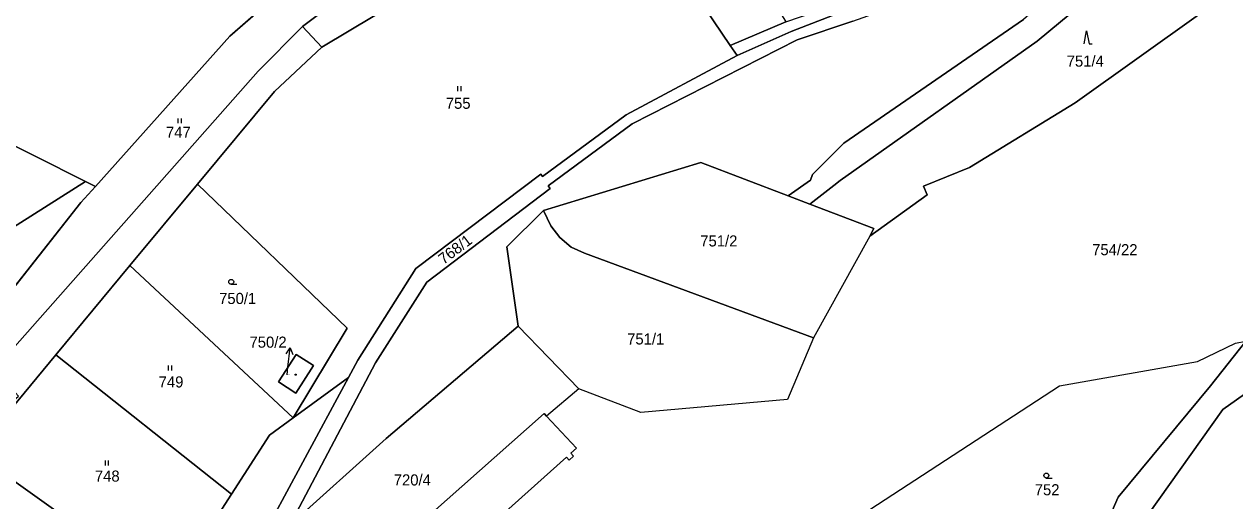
# Model space of a CAD drawing. Extents: x -598233 to -596890, y -1157848 to -1156431.
# Drawn here: x -597461.1 to -597275.6, y -1157216.3 to -1157143.3 of the extents above; entities that cross this region are included whole.
import ezdxf

# ---------------------------------------------------------------- set-up
doc = ezdxf.new("R2010")
doc.units = 0
for name, color, linetype in [('Level 1', 7, 'Continuous'), ('Level 4', 7, 'Continuous'), ('Level 5', 7, 'Continuous'), ('Level 57', 7, 'Continuous'), ('Level 60', 7, 'Continuous'), ('Vrstva 54', 7, 'Continuous'), ('Vrstva 60', 7, 'Continuous')]:
    doc.layers.add(name, color=color, linetype=linetype)

msp = doc.modelspace()

# ---------------------------------------------------------------- linework, layer by layer
at = {"layer": 'Level 1'}
for points in [[(-597420.41, -1157220.01), (-597407.32, -1157195.13), (-597399.45, -1157182.8), (-597380.53, -1157168.45), (-597380.82, -1157168.06), (-597367.96, -1157158.55), (-597342.68, -1157145.66), (-597334.13, -1157142.8), (-597316.39, -1157136.47), (-597308.16, -1157133.06), (-597297.58, -1157125.35), (-597289.89, -1157118.41), (-597284.19, -1157108.45), (-597281.93, -1157098.65), (-597282.12, -1157088.82), (-597281.12, -1157079.45), (-597275.24, -1157065.47), (-597273.04, -1157056.33), (-597273.21, -1157044.87), (-597272.14, -1157037.1)], [(-597272.14, -1157037.1), (-597265.05, -1157046.04), (-597261.79, -1157055.57), (-597266.72, -1157090.16), (-597273.93, -1157106.57), (-597277.61, -1157115.85), (-597307.94, -1157142.59), (-597335.53, -1157161.51), (-597340.31, -1157166.32), (-597340.61, -1157167.15), (-597344.04, -1157169.58)], [(-597450.24, -1157168.12), (-597429.64, -1157145.11), (-597411.66, -1157129.43), (-597398.16, -1157121.72), (-597386.77, -1157115.26), (-597350.78, -1157099.58), (-597323.95, -1157090.2), (-597313.81, -1157082.16), (-597315.54, -1157068.55), (-597316.36, -1157049.69)], [(-597351.85, -1157148.1), (-597343.59, -1157144.39), (-597334.76, -1157141.01), (-597316.98, -1157135.11), (-597308.9, -1157131.83), (-597298.55, -1157124.28), (-597291.05, -1157117.54), (-597285.6, -1157107.91), (-597283.46, -1157098.39), (-597283.52, -1157096.39)], [(-597269.15, -1157107.01), (-597274.89, -1157120.22), (-597305.88, -1157145.91), (-597336.09, -1157167.23), (-597337.03, -1157167.99), (-597340.73, -1157170.84)], [(-597331.54, -1157175.75), (-597322.73, -1157169.4), (-597323.3, -1157168.1), (-597316.26, -1157165.22), (-597300.02, -1157155.33), (-597280.79, -1157141.61), (-597273.23, -1157122.89), (-597269.15, -1157107.01)], [(-597369.95, -1157114.08), (-597393.69, -1157127.25), (-597407.09, -1157135.08), (-597418.47, -1157143.66)], [(-597553.97, -1157115.98), (-597451.73, -1157167.37)], [(-597369.32, -1157122.27), (-597389.93, -1157131.92), (-597403.46, -1157139.6), (-597415.52, -1157146.8)], [(-597369.32, -1157122.27), (-597352.91, -1157146.54)], [(-597524.08, -1157216.07), (-597496.65, -1157207.84), (-597474.26, -1157198.23), (-597452.46, -1157170.6), (-597450.24, -1157168.12), (-597429.64, -1157145.11), (-597411.66, -1157129.43)], [(-597465.75, -1157196.15), (-597425.29, -1157150.48), (-597418.47, -1157143.66)], [(-597418.47, -1157143.66), (-597415.52, -1157146.8)], [(-597352.91, -1157146.54), (-597344.41, -1157142.92)], [(-597415.52, -1157146.8), (-597422.79, -1157153.6), (-597434.59, -1157167.79)], [(-597352.91, -1157146.54), (-597351.85, -1157148.1)], [(-597351.85, -1157148.1), (-597368.85, -1157157.16), (-597381.69, -1157166.63), (-597381.96, -1157166.26), (-597401.12, -1157180.72), (-597410, -1157194.72), (-597411.46, -1157197.37)], [(-597344.04, -1157169.58), (-597357.42, -1157164.48), (-597381.55, -1157171.84)], [(-597524.08, -1157216.07), (-597517.72, -1157209.12), (-597451.73, -1157167.37)], [(-597451.73, -1157167.37), (-597450.24, -1157168.12)], [(-597450.24, -1157168.12), (-597452.46, -1157170.6), (-597474.26, -1157198.23), (-597496.65, -1157207.84), (-597524.08, -1157216.07)], [(-597444.95, -1157180.26), (-597434.59, -1157167.79)], [(-597419.9, -1157203.55), (-597411.62, -1157189.83), (-597434.59, -1157167.79)], [(-597344.04, -1157169.58), (-597340.73, -1157170.84)], [(-597340.73, -1157170.84), (-597330.89, -1157174.58), (-597331.54, -1157175.75)], [(-597381.55, -1157171.84), (-597387.15, -1157177.39), (-597385.41, -1157189.54)], [(-597381.55, -1157171.84), (-597380.42, -1157174.15), (-597379.04, -1157175.95), (-597377.3, -1157177.42), (-597375.26, -1157178.33), (-597340.14, -1157191.3)], [(-597331.54, -1157175.75), (-597340.14, -1157191.3)], [(-597456.32, -1157193.94), (-597444.95, -1157180.26)], [(-597419.9, -1157203.55), (-597444.95, -1157180.26)], [(-597420.41, -1157220.01), (-597405.66, -1157206.73), (-597385.41, -1157189.54)], [(-597385.41, -1157189.54), (-597376.12, -1157199.13)], [(-597340.14, -1157191.3), (-597344.15, -1157200.78), (-597366.64, -1157202.74), (-597376.12, -1157199.13)], [(-597273.89, -1157191.83), (-597279.31, -1157198.65), (-597293.44, -1157215.73), (-597305.02, -1157242.05)], [(-597362.93, -1157237.24), (-597355.27, -1157226.91), (-597332.68, -1157218.37), (-597302.46, -1157198.67), (-597281.27, -1157194.94), (-597275.47, -1157192.13)], [(-597456.32, -1157193.94), (-597466.04, -1157205.64), (-597469.84, -1157208.12)], [(-597429.37, -1157215.26), (-597456.32, -1157193.94)], [(-597419.49, -1157199.79), (-597416.82, -1157195.56), (-597419.47, -1157193.87), (-597422.17, -1157198.06), (-597419.49, -1157199.79)], [(-597411.46, -1157197.37), (-597425.45, -1157223.34), (-597427.91, -1157230.87), (-597427.85, -1157244.2)], [(-597419.9, -1157203.55), (-597411.46, -1157197.37)], [(-597268.17, -1157195.77), (-597277.39, -1157202.28), (-597290.48, -1157220.66), (-597300.86, -1157251.86), (-597302.5, -1157270.51), (-597302.01, -1157282.08), (-597299.14, -1157291.81), (-597291.38, -1157303.96)], [(-597376.12, -1157199.13), (-597381.09, -1157203.29)], [(-597381.09, -1157203.29), (-597381.46, -1157202.9), (-597408.92, -1157227.27)], [(-597429.37, -1157215.26), (-597423.55, -1157206.23), (-597419.9, -1157203.55)], [(-597381.09, -1157203.29), (-597376.48, -1157208.23), (-597377.33, -1157208.99), (-597376.93, -1157209.44), (-597377.61, -1157210.03), (-597378.01, -1157209.58), (-597404, -1157232.83)], [(-597463.07, -1157212.95), (-597438.96, -1157230.16)], [(-597429.37, -1157215.26), (-597438.96, -1157230.16)]]:
    msp.add_lwpolyline(points, dxfattribs=at)
at = {"layer": 'Level 5'}
for p, q in [((-597394.68, -1157153.55), (-597394.68, -1157152.8)), ((-597394.18, -1157153.55), (-597394.18, -1157152.8)), ((-597437.54, -1157158.47), (-597437.54, -1157157.71)), ((-597437.04, -1157158.47), (-597437.04, -1157157.71)), ((-597429.41, -1157183.12), (-597428.54, -1157183.12)), ((-597439.03, -1157196.31), (-597439.03, -1157195.56)), ((-597438.53, -1157196.31), (-597438.53, -1157195.56)), ((-597448.7, -1157210.88), (-597448.7, -1157210.12)), ((-597448.2, -1157210.88), (-597448.2, -1157210.12)), ((-597304.47, -1157212.79), (-597303.59, -1157212.79))]:
    msp.add_line(p, q, dxfattribs=at)
msp.add_lwpolyline([(-597298.67, -1157146.29), (-597298.29, -1157144.29), (-597297.92, -1157146.29), (-597297.42, -1157146.29)], dxfattribs=at)
for centre, radius in [((-597429.41, -1157182.74), 0.375), ((-597419.54, -1157196.96), 0.09), ((-597419.54, -1157196.96), 0.0521), ((-597304.47, -1157212.41), 0.375)]:
    msp.add_circle(centre, radius, dxfattribs=at)
at = {"layer": 'Level 57'}
for p, q in [((-597420.71, -1157195.81), (-597420.36, -1157192.83)), ((-597420.85, -1157196.98), (-597420.71, -1157195.81))]:
    msp.add_line(p, q, dxfattribs=at)
msp.add_lwpolyline([(-597420.97, -1157193.76), (-597420.36, -1157192.83), (-597419.98, -1157193.88)], dxfattribs=at)
at = {"layer": 'Level 60'}
for points in [[(-597307.81, -1157084.74), (-597301.66, -1157087.52), (-597298.35, -1157089.14), (-597305.98, -1157091.3), (-597309.72, -1157094.65), (-597316.07, -1157099.31), (-597317.89, -1157100.18), (-597330.11, -1157105.15), (-597340.32, -1157109.16), (-597349.85, -1157113.62), (-597359.61, -1157117.9), (-597369.32, -1157122.27), (-597389.93, -1157131.92), (-597403.46, -1157139.6), (-597415.52, -1157146.8), (-597418.47, -1157143.66), (-597407.09, -1157135.08), (-597393.69, -1157127.25), (-597369.95, -1157114.08), (-597346.8, -1157104.38), (-597328.8, -1157098.51), (-597317.13, -1157092.88)], [(-597352.91, -1157146.54), (-597344.41, -1157142.92), (-597335.26, -1157139.83), (-597326.31, -1157136.94), (-597317.39, -1157134.04), (-597309.65, -1157130.62), (-597299.16, -1157123.62), (-597294.28, -1157119.17), (-597291.86, -1157116.61), (-597288.44, -1157110.8), (-597285.51, -1157101.67), (-597284.71, -1157097.77), (-597285.24, -1157095.55), (-597283.52, -1157096.39), (-597283.46, -1157098.39), (-597285.6, -1157107.91), (-597291.05, -1157117.54), (-597298.55, -1157124.28), (-597308.9, -1157131.83), (-597316.98, -1157135.11), (-597334.76, -1157141.01), (-597343.59, -1157144.39), (-597351.85, -1157148.1)], [(-597316.26, -1157165.22), (-597323.3, -1157168.1), (-597322.73, -1157169.4), (-597331.54, -1157175.75), (-597330.89, -1157174.58), (-597340.73, -1157170.84), (-597337.03, -1157167.99), (-597336.09, -1157167.23), (-597305.88, -1157145.91), (-597274.89, -1157120.22), (-597269.15, -1157107.01), (-597273.23, -1157122.89), (-597280.79, -1157141.61), (-597300.02, -1157155.33)], [(-597452.46, -1157170.6), (-597450.24, -1157168.12), (-597429.64, -1157145.11), (-597411.66, -1157129.43), (-597390.96, -1157122.26), (-597369.95, -1157114.08), (-597393.69, -1157127.25), (-597407.09, -1157135.08), (-597418.47, -1157143.66), (-597425.29, -1157150.48), (-597465.75, -1157196.15), (-597476.19, -1157204.35), (-597475.96, -1157204.86), (-597480.59, -1157207.63), (-597507.42, -1157213.91), (-597524.08, -1157216.07), (-597496.65, -1157207.84), (-597474.26, -1157198.23)], [(-597344.41, -1157142.92), (-597352.91, -1157146.54), (-597369.32, -1157122.27), (-597359.61, -1157117.9)], [(-597403.46, -1157139.6), (-597389.93, -1157131.92), (-597369.32, -1157122.27), (-597352.91, -1157146.54), (-597351.85, -1157148.1), (-597368.85, -1157157.16), (-597381.69, -1157166.63), (-597381.96, -1157166.26), (-597401.12, -1157180.72), (-597410, -1157194.72), (-597411.46, -1157197.37), (-597419.9, -1157203.55), (-597411.62, -1157189.83), (-597434.59, -1157167.79), (-597422.79, -1157153.6), (-597415.52, -1157146.8)], [(-597476.64, -1157212.54), (-597512.61, -1157220.64), (-597524.62, -1157222.61), (-597531.88, -1157225.36), (-597527.01, -1157220.76), (-597524.08, -1157216.07), (-597507.42, -1157213.91), (-597480.59, -1157207.63), (-597475.96, -1157204.86), (-597473.92, -1157209.39), (-597468.46, -1157205.88), (-597462.02, -1157200.24), (-597465.75, -1157196.15), (-597425.29, -1157150.48), (-597418.47, -1157143.66), (-597415.52, -1157146.8), (-597422.79, -1157153.6), (-597434.59, -1157167.79), (-597444.95, -1157180.26), (-597456.32, -1157193.94), (-597466.04, -1157205.64), (-597469.84, -1157208.12)], [(-597375.26, -1157178.33), (-597377.3, -1157177.42), (-597379.04, -1157175.95), (-597380.42, -1157174.15), (-597381.55, -1157171.84), (-597357.42, -1157164.48), (-597344.04, -1157169.58), (-597340.73, -1157170.84), (-597330.89, -1157174.58), (-597331.54, -1157175.75), (-597340.14, -1157191.3)], [(-597524.08, -1157216.07), (-597517.72, -1157209.12), (-597451.73, -1157167.37), (-597450.24, -1157168.12), (-597452.46, -1157170.6), (-597474.26, -1157198.23), (-597496.65, -1157207.84)], [(-597444.95, -1157180.26), (-597434.59, -1157167.79), (-597411.62, -1157189.83), (-597419.9, -1157203.55)], [(-597340.14, -1157191.3), (-597344.15, -1157200.78), (-597366.64, -1157202.74), (-597376.12, -1157199.13), (-597385.41, -1157189.54), (-597387.15, -1157177.39), (-597381.55, -1157171.84), (-597380.42, -1157174.15), (-597379.04, -1157175.95), (-597377.3, -1157177.42), (-597375.26, -1157178.33)], [(-597423.55, -1157206.23), (-597429.37, -1157215.26), (-597456.32, -1157193.94), (-597444.95, -1157180.26), (-597419.9, -1157203.55)], [(-597381.09, -1157203.29), (-597381.46, -1157202.9), (-597408.92, -1157227.27), (-597419.97, -1157235.64), (-597420.6, -1157236.56), (-597421.32, -1157239.68), (-597421.1, -1157246.07), (-597423.13, -1157248.49), (-597424.67, -1157248.22), (-597424.87, -1157240.37), (-597424.77, -1157237.25), (-597423.67, -1157233.2), (-597422.12, -1157230.53), (-597421.61, -1157229.7), (-597422.51, -1157228.92), (-597422.7, -1157225.56), (-597420.41, -1157220.01), (-597405.66, -1157206.73), (-597385.41, -1157189.54), (-597376.12, -1157199.13)], [(-597302.46, -1157198.67), (-597281.27, -1157194.94), (-597275.47, -1157192.13), (-597273.89, -1157191.83), (-597279.31, -1157198.65), (-597293.44, -1157215.73), (-597305.02, -1157242.05), (-597317.96, -1157228.85), (-597330.51, -1157222.48), (-597340.87, -1157222.41), (-597352.41, -1157227.93), (-597362.93, -1157237.24), (-597355.27, -1157226.91), (-597332.68, -1157218.37)], [(-597438.96, -1157230.16), (-597463.07, -1157212.95), (-597469.84, -1157208.12), (-597466.04, -1157205.64), (-597456.32, -1157193.94), (-597429.37, -1157215.26)], [(-597416.82, -1157195.56), (-597419.49, -1157199.79), (-597422.17, -1157198.06), (-597419.47, -1157193.87)], [(-597419.49, -1157199.79), (-597416.82, -1157195.56), (-597419.47, -1157193.87), (-597422.17, -1157198.06)], [(-597429.37, -1157215.26), (-597423.55, -1157206.23), (-597419.9, -1157203.55), (-597411.46, -1157197.37), (-597425.45, -1157223.34), (-597427.91, -1157230.87), (-597427.85, -1157244.2), (-597438.96, -1157230.16)], [(-597381.46, -1157202.9), (-597381.09, -1157203.29), (-597376.48, -1157208.23), (-597377.33, -1157208.99), (-597376.93, -1157209.44), (-597377.61, -1157210.03), (-597378.01, -1157209.58), (-597404, -1157232.83), (-597408.92, -1157227.27)]]:
    msp.add_lwpolyline(points, close=True, dxfattribs=at)
for points in [[(-597553.97, -1157115.98), (-597451.73, -1157167.37), (-597517.72, -1157209.12), (-597524.08, -1157216.07), (-597544.75, -1157236.3), (-597553.08, -1157244.43), (-597572.6, -1157270.07), (-597583.83, -1157284.82), (-597594.92, -1157321.55), (-597720.07, -1157265.02), (-597697.73, -1157214.64), (-597717.33, -1157206.86), (-597734.08, -1157200.94), (-597757.16, -1157192.27), (-597776.1, -1157174.66), (-597802.39, -1157227.84), (-597822.9, -1157218.58), (-597805.12, -1157122.39)], [(-597411.66, -1157129.43), (-597429.64, -1157145.11), (-597450.24, -1157168.12), (-597451.73, -1157167.37), (-597553.97, -1157115.98)], [(-597274.89, -1157120.22), (-597305.88, -1157145.91), (-597336.09, -1157167.23), (-597337.03, -1157167.99), (-597340.73, -1157170.84), (-597344.04, -1157169.58), (-597340.61, -1157167.15), (-597340.31, -1157166.32), (-597335.53, -1157161.51), (-597307.94, -1157142.59)], [(-597425.45, -1157223.34), (-597411.46, -1157197.37), (-597410, -1157194.72), (-597401.12, -1157180.72), (-597381.96, -1157166.26), (-597381.69, -1157166.63), (-597368.85, -1157157.16), (-597351.85, -1157148.1), (-597343.59, -1157144.39), (-597334.76, -1157141.01)], [(-597307.94, -1157142.59), (-597335.53, -1157161.51), (-597340.31, -1157166.32), (-597340.61, -1157167.15), (-597344.04, -1157169.58), (-597357.42, -1157164.48), (-597381.55, -1157171.84), (-597387.15, -1157177.39), (-597385.41, -1157189.54), (-597405.66, -1157206.73), (-597420.41, -1157220.01), (-597407.32, -1157195.13), (-597399.45, -1157182.8), (-597380.53, -1157168.45), (-597380.82, -1157168.06), (-597367.96, -1157158.55), (-597342.68, -1157145.66), (-597334.13, -1157142.8)], [(-597334.13, -1157142.8), (-597342.68, -1157145.66), (-597367.96, -1157158.55), (-597380.82, -1157168.06), (-597380.53, -1157168.45), (-597399.45, -1157182.8), (-597407.32, -1157195.13), (-597420.41, -1157220.01)], [(-597305.02, -1157242.05), (-597293.44, -1157215.73), (-597279.31, -1157198.65), (-597273.89, -1157191.83)], [(-597271.47, -1157322.1), (-597277.04, -1157322.56), (-597291.38, -1157303.96), (-597299.14, -1157291.81), (-597302.01, -1157282.08), (-597302.5, -1157270.51), (-597300.86, -1157251.86), (-597290.48, -1157220.66), (-597277.39, -1157202.28), (-597268.17, -1157195.77)], [(-597268.17, -1157195.77), (-597277.39, -1157202.28), (-597290.48, -1157220.66)], [(-597463.07, -1157212.95), (-597438.96, -1157230.16), (-597445.33, -1157253.98), (-597451.76, -1157258.32), (-597452.66, -1157255.64), (-597462.64, -1157226.12)]]:
    msp.add_lwpolyline(points, dxfattribs=at)
at = {"layer": 'Vrstva 54'}
for p, q in [((-597411.66, -1157129.43), (-597429.64, -1157145.11)), ((-597429.64, -1157145.11), (-597450.24, -1157168.12)), ((-597450.24, -1157168.12), (-597452.46, -1157170.6)), ((-597452.46, -1157170.6), (-597474.26, -1157198.23))]:
    msp.add_line(p, q, dxfattribs=at)
at = {"layer": 'Vrstva 60'}
for points in [[(-597411.66, -1157129.43), (-597429.64, -1157145.11), (-597450.24, -1157168.12), (-597452.46, -1157170.6), (-597474.26, -1157198.23)], [(-597474.26, -1157198.23), (-597452.46, -1157170.6), (-597450.24, -1157168.12), (-597429.64, -1157145.11), (-597411.66, -1157129.43)], [(-597280.79, -1157141.61), (-597300.02, -1157155.33), (-597316.26, -1157165.22), (-597323.3, -1157168.1), (-597322.73, -1157169.4), (-597331.54, -1157175.75), (-597340.14, -1157191.3), (-597344.15, -1157200.78), (-597366.64, -1157202.74), (-597376.12, -1157199.13), (-597381.09, -1157203.29), (-597376.48, -1157208.23), (-597377.33, -1157208.99), (-597376.93, -1157209.44), (-597377.61, -1157210.03), (-597378.01, -1157209.58), (-597404, -1157232.83)], [(-597332.68, -1157218.37), (-597302.46, -1157198.67), (-597281.27, -1157194.94), (-597275.47, -1157192.13)]]:
    msp.add_lwpolyline(points, dxfattribs=at)

# ---------------------------------------------------------------- texts
at = {"layer": 'Level 4'}
for s, height, p in [('751/4', 1.7, (-597301.34, -1157149.79)), ('755', 1.7, (-597396.52, -1157156.25)), ('747', 1.7, (-597439.42, -1157160.69)), ('751/2', 1.7, (-597357.51, -1157177.33)), ('750/1', 1.7, (-597431.27, -1157186.14)), ('751/1', 1.7, (-597368.72, -1157192.34)), ('749', 1.7, (-597440.54, -1157198.92)), ('750/2', 0.1, (-597420.85, -1157196.98)), ('748', 1.7, (-597450.31, -1157213.34)), ('720/4', 1.7, (-597404.5, -1157213.93)), ('752', 1.7, (-597306.24, -1157215.43))]:
    msp.add_text(s, height=height, dxfattribs=at).set_placement(p)
msp.add_text('768/1', height=1.7, rotation=37.2079, dxfattribs=at).set_placement((-597396.85, -1157180.17))
at = {"layer": 'Level 57'}
for s, p in [('754/22', (-597297.44, -1157178.67)), ('750/2', (-597426.61, -1157192.83))]:
    msp.add_text(s, height=1.7, dxfattribs=at).set_placement(p)

doc.saveas('drawing.dxf')
